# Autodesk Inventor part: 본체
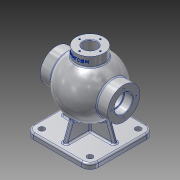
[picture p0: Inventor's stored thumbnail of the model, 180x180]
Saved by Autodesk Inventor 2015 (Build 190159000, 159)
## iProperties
Created: 2025-08
Part Number: 본체
Material: 알루미늄 6061
Document SubType Name: Modeling
Designer: USER
Density: 2.7 g/cm^3
Appearance: 알루미늄 - 평지
Mass: 1526.68 g
Surface Area: 1174.39 cm^2
Volume: 565.437 cm^3
Author: USER
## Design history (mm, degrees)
sketch "스케치1"
  geometry: L1 (-62.5, 62.5)-(62.5, 62.5); L2 (62.5, 62.5)-(62.5, -62.5); L3 (62.5, -62.5)-(-62.5, -62.5); L4 (-62.5, -62.5)-(-62.5, 62.5); L5 (-62.5, 62.5)-(62.5, -62.5); L6 (62.5, 62.5)-(-62.5, -62.5); 1 further point
  constraints: 12 end point, 2 midpoint, 2 parallel, 1 horizontal, 1 perpendicular
  dimensions: "d0" = 125 distance of L2.end L3.end; "d1" = 125 distance of L1.end L2.end
extrude "돌출1" new body sketch "스케치1" distance "d2" = 10; taper "d3" = 0 deg
sketch "스케치3"
  geometry: L1 (62.5, 0)-(-62.5, 0) reference; L2 (62.5, 0)-(62.5, 10) reference; L3 (-62.5, 10)-(62.5, 10) reference; L4 (-62.5, 0)-(-62.5, 10) reference; L5 (0, 0)-(0, 85); L6 (65, 85)-(-65, 85); L7 (-65, 85)-(-65, 54); L8 (-65, 54)-(-44.215, 54); L9 (65, 85)-(65, 54); L10 (65, 54)-(44.215, 54); A1 r 44 centre (0, 85) between (-44, 85) and (44, 85); A2 r 54 centre (0, 85) between (-44.215, 54) and (44.215, 54)
  constraints: 12 end point, 4 point on circle, 3 perpendicular, 2 centre point, 2 coincident, 2 point on line, 2 vertical, 1 horizontal, 1 other
  dimensions: "d15" = 85 distance of L5.start L5.end; "d16" = 88 diameter of A1; "d18" = 31 distance of L6.end L7.end; "d19" = 31 distance of L6.start L9.end; "d20" = 130 distance of L6.start L6.end; "d21" = 20.78462 distance of L9.end L10.end; "d22" = 85 vertical distance of L1.end L6.end
revolve "회전2" sketch "스케치3" stored, may be unused: angle "d23" = 90 deg
sketch "스케치4"
  geometry: L1 (-62.5, 62.5)-(62.5, 62.5) reference; L2 (62.5, 62.5)-(62.5, -62.5) reference; L3 (62.5, -62.5)-(-62.5, -62.5) reference; L4 (-62.5, -62.5)-(-62.5, 62.5) reference; L5 (-4, 50.5)-(4, 50.5); L6 (4, 50.5)-(4, -50.5); L7 (4, -50.5)-(-4, -50.5); L8 (-4, -50.5)-(-4, 50.5); L9 (0, 0)-(0, 21.004); L10 (-50.5, 4)-(50.5, 4); L11 (50.5, 4)-(50.5, -4); L12 (50.5, -4)-(-50.5, -4); L13 (-50.5, -4)-(-50.5, 4); L14 (0, 0)-(26.971, 0)
  constraints: 20 end point, 5 parallel, 3 horizontal, 2 perpendicular, 2 other
  dimensions: "d24" = 8 distance of L5.start L5.end; "d25" = 12 vertical distance of L5.end L1.end; "d26" = 12 vertical distance of L2.end L6.end; "d27" = 8 distance of L12.end L10.start; "d28" = 12 horizontal distance of L1.start L10.start; "d29" = 12 horizontal distance of L2.end L11.end
extrude "돌출2" join sketch "스케치4" stored distance "d30" = 80; taper "d31" = 0 deg
feature "면 기울기1" dims angle "d32" = 20 deg
feature "면 기울기2" dims angle "d33" = 20 deg
feature "면 기울기3" dims angle "d34" = 20 deg
feature "면 기울기4" dims angle "d35" = 20 deg
node "작업 평면6"
sketch "스케치6"
  geometry: C1 r 27 at (0, 0); 1 further point
  constraints: 1 centre point, 1 coincident
  dimensions: "d39" = 54 diameter of C1
extrude "돌출3" join sketch "스케치6" stored distance "d40" = 80; taper "d41" = 0 deg
hole "구멍1" diameter "d44" = 30; stored, may be unused: countersink angle "d48" = 90 deg, drill point angle "d50" = 118 deg; dims "d42" = 10, "d43" = 10, "d45" = 6, "d46" = 35, "d47" = 16, "d49" = 8
hole "구멍2" diameter "d53" = 26; stored, may be unused: countersink angle "d57" = 90 deg, drill point angle "d59" = 118 deg; dims "d51" = 10, "d52" = 10, "d54" = 6, "d55" = 35, "d56" = 16, "d58" = 50
sketch "스케치7"
  geometry: L1 (0, 0)-(24, 0); C1 r 15 at (0, 0) reference; 1 further point
  constraints: 2 end point, 1 horizontal
  dimensions: "d60" = 24 distance of L1.start L1.end
hole "구멍3" sketch "스케치7" at (24, 0) diameter "d61" = 3.242; stored, may be unused: countersink angle "d65" = 90 deg, drill point angle "d67" = 118 deg; dims "d62" = 12, "d63" = 35, "d64" = 16, "d66" = 15
sketch "스케치8"
  geometry: L1 (0, 0)-(0, 20)
  constraints: 2 end point, 1 vertical
  dimensions: "d71" = 20 distance of L1.start L1.end
hole "구멍4" sketch "스케치8" at (0, 20) diameter "d72" = 3.242; stored, may be unused: countersink angle "d76" = 90 deg, drill point angle "d78" = 118 deg; dims "d73" = 9, "d74" = 35, "d75" = 16, "d77" = 11
fillet "모깎기1" dims "d82" = 16
hole "구멍5" diameter "d85" = 11; stored, may be unused: countersink angle "d89" = 90 deg, drill point angle "d91" = 118 deg; dims "d83" = 10, "d84" = 10, "d86" = 9, "d87" = 35, "d88" = 16, "d90" = 11
hole "구멍6" diameter "d94" = 11; stored, may be unused: countersink angle "d98" = 90 deg, drill point angle "d100" = 118 deg; dims "d92" = 10, "d93" = 10, "d95" = 9, "d96" = 35, "d97" = 16, "d99" = 11
hole "구멍7" diameter "d103" = 11; stored, may be unused: countersink angle "d107" = 90 deg, drill point angle "d109" = 118 deg; dims "d101" = 10, "d102" = 10, "d104" = 9, "d105" = 35, "d106" = 16, "d108" = 11
hole "구멍8" diameter "d112" = 11; stored, may be unused: countersink angle "d116" = 90 deg, drill point angle "d118" = 118 deg; dims "d110" = 10, "d111" = 10, "d113" = 9, "d114" = 35, "d115" = 16, "d117" = 11
node "작업 평면7"
sketch "스케치9"
  geometry: L1 (-27, 150)-(27, 150) reference; 2 further points
  constraints: 1 vertical alignment, 1 other
  dimensions: "d120" = 9 distance from line of point (0, 141) L1
feature "엠보싱1" sketch "스케치9" dims "d0" = 125, "d1" = 125, "d121" = 0.5, "d122" = 0
fillet "모깎기2" dims "d123" = 3
fillet "모깎기3" dims "d124" = 3
fillet "모깎기4" dims "d125" = 3
chamfer "모따기1" distance "d126" = 1; stored, may be unused: second distance "d127" = 2, angle "d128" = 45 deg
fillet "모깎기5" dims "d129" = 0.6
node "솔리드1"
mirror "대칭1"
pattern_circular "원형 패턴1" dims angle "d69" = 360 deg
mirror "대칭2"
pattern_circular "원형 패턴2" dims angle "d80" = 360 deg
node "투영된 루프1"
node "투영된 루프2"
other parameters: "d17" = 108, "d119" = -106.75
